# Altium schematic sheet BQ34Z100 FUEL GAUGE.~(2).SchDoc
size A3; SheetNumber: 13; SheetTotal: 14
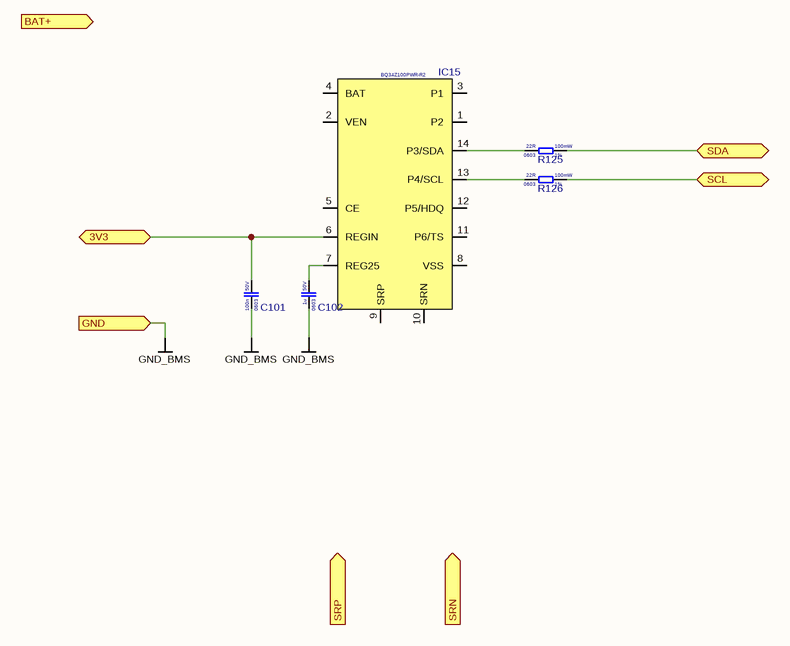
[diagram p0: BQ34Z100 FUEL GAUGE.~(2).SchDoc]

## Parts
C101  Voltage Rating: 50V  Case Code (Imperial): 0603  Capacitance: 100n  [CAP 0603]  (hidden comment: CC0603KRX7R9BB104)
C102  Voltage Rating: 50V  Case Code (Imperial): 0603  Capacitance: 1u  [CAP 0603]  (hidden comment: CL10A105KB8NNNC)
IC15  BQ34Z100PWR-R2  [TSSOP-14]
R125  Resistance Tolerance: 1%  Resistance: 22R  Power Rating: 100mW  Case Code (Imperial): 0603  [RES_0603]  (hidden comment: 0603WAF220JT5E)
R126  Resistance Tolerance: 1%  Resistance: 22R  Power Rating: 100mW  Case Code (Imperial): 0603  [RES_0603]  (hidden comment: 0603WAF220JT5E)

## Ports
3V3 (bidir, see BMS[4C], 5V to 3V3 LDO[5B]), BAT+ (in, see BMS[4D], BAT+ to 5V1 STEP-DOWN[3B], BMS[1A], BQ76952 BMS[1A]), GND (in, see BMS[4D], 5V to 3V3 LDO[3B], BAT+ to 5V1 STEP-DOWN[3C], BQ76952 BMS[1D], MCU[1C]), SCL (bidir, see BMS[4C], BMS[8C], BQ76952 BMS[7C], MCU[1B]), SDA (bidir, see BMS[4C], BMS[8C], BQ76952 BMS[7C], MCU[1B]), SRN (in, see BMS[4D], BQ76952 BMS[5D]), SRP (in, see BMS[4D], BQ76952 BMS[5D])

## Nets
GND_BMS: C101.1 C102.1 ; port GND
3V3: C101.2 IC15.6(REGIN) ; port 3V3
SCL: R126.2 ; port SCL
SDA: R125.2 ; port SDA
NetC102_2: C102.2 IC15.7(REG25)
NetIC15_13: IC15.13(P4/SCL) R126.1
NetIC15_14: IC15.14(P3/SDA) R125.1

Not connected (* = marked no-connect by the designer): IC15 1(P2) 2(VEN) 3(P1) 4(BAT) 5(CE) 8(VSS) 9(SRP) 10(SRN) 11(P6/TS) 12(P5/HDQ)

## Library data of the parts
C101 = CC0603KRX7R9BB104: Cap 100nF 50V 0603 X7R; Manufacturer: Yageo
C102 = CL10A105KB8NNNC: Cap 1uF 50V 0603 X5R; Manufacturer: Samsung
IC15 = BQ34Z100PWR-R2: Fuel gauge; Manufacturer: Texas Instruments
R125 R126 = 0603WAF220JT5E: Res 22R 0603 1% 100mW 75V; Manufacturer: Uni-Royal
